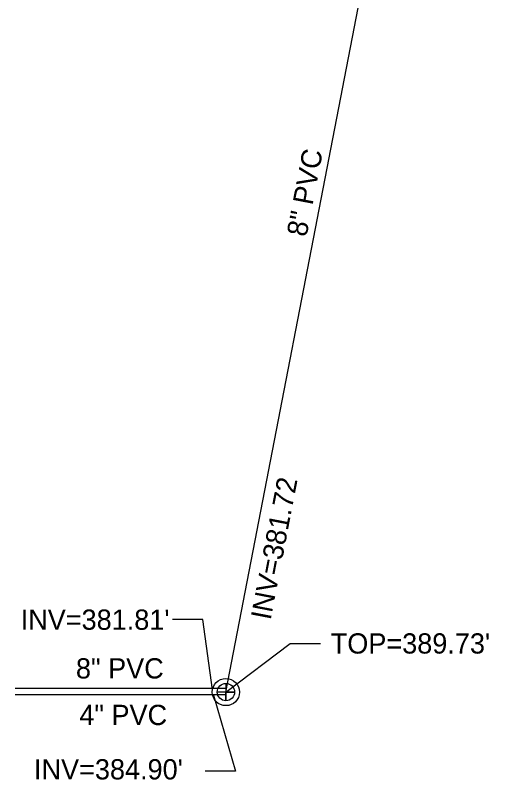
# Model space of a CAD drawing. Extents: x 2089016 to 2094354, y 862840 to 864725.
# Drawn here: x 2092948.1 to 2093042.5, y 863224.4 to 863375.4 of the extents above; entities that cross this region are included whole.
import ezdxf

# ---------------------------------------------------------------- set-up
doc = ezdxf.new("R2010")
doc.units = 0
for name, color, linetype in [('Exist Utilities Sanitary Sewer Manhole Leader', 7, 'Continuous'), ('Exist Utilities Sanitary Sewer Manhole Text', 7, 'Continuous'), ('Exist Utilities Sanitary Sewer UG Line', 7, 'Continuous'), ('Exist Utilities Sanitary Sewer UG Line Invert Elevation', 7, 'Continuous'), ('Exist Utilities Sanitary Sewer UG Line Leader', 7, 'Continuous'), ('Exist Utilities Sanitary Sewer UG Line Text', 7, 'Continuous'), ('Raster_Level_0', 7, 'Continuous')]:
    doc.layers.add(name, color=color, linetype=linetype)

msp = doc.modelspace()

# ---------------------------------------------------------------- linework, layer by layer
at = {"layer": 'Exist Utilities Sanitary Sewer Manhole Leader'}
msp.add_lwpolyline([(2092989.74, 863241.76), (2093002.46, 863251.36), (2093008.46, 863251.36)], dxfattribs=at)
at = {"layer": 'Exist Utilities Sanitary Sewer UG Line'}
for p, q in [((2092989.74, 863241.76), (2093042.48, 863514.23)), ((2092989.74, 863242.44), (2092948.1, 863242.44)), ((2092989.74, 863241.24), (2092948.1, 863241.24))]:
    msp.add_line(p, q, dxfattribs=at)
at = {"layer": 'Exist Utilities Sanitary Sewer UG Line Leader'}
for points in [[(2092987.07, 863242.18), (2092985.19, 863256.06), (2092979.19, 863256.06)], [(2092987.29, 863241.15), (2092991.61, 863226.11), (2092985.61, 863226.11)]]:
    msp.add_lwpolyline(points, dxfattribs=at)
at = {"layer": 'Raster_Level_0'}
msp.add_lwpolyline([(2092989.74, 863243.47), (2092989.74, 863240.04), (2092989.74, 863241.76), (2092991.45, 863241.76), (2092988.03, 863241.76)], dxfattribs=at)
for radius in [2.69, 1.71]:
    msp.add_circle((2092989.74, 863241.76), radius, dxfattribs=at)

# ---------------------------------------------------------------- texts
at = {"layer": 'Exist Utilities Sanitary Sewer Manhole Text'}
msp.add_text("TOP=389.73'", height=4, dxfattribs=at).set_placement((2093010.46, 863249.36))
at = {"layer": 'Exist Utilities Sanitary Sewer UG Line Invert Elevation'}
msp.add_text('INV=381.72', height=4, rotation=79.1247, dxfattribs=at).set_placement((2092998.56, 863255.84))
for s, p in [("INV=381.81'", (2092949.17, 863254.06)), ("INV=384.90'", (2092951.8, 863224.5))]:
    msp.add_text(s, height=4, dxfattribs=at).set_placement(p)
at = {"layer": 'Exist Utilities Sanitary Sewer UG Line Text'}
msp.add_text('8" PVC', height=4, rotation=79.1247, dxfattribs=at).set_placement((2093005.65, 863331.53))
for s, p in [('8" PVC', (2092960.09, 863244.44)), ('4" PVC', (2092960.76, 863235.24))]:
    msp.add_text(s, height=4, dxfattribs=at).set_placement(p)

doc.saveas('drawing.dxf')
